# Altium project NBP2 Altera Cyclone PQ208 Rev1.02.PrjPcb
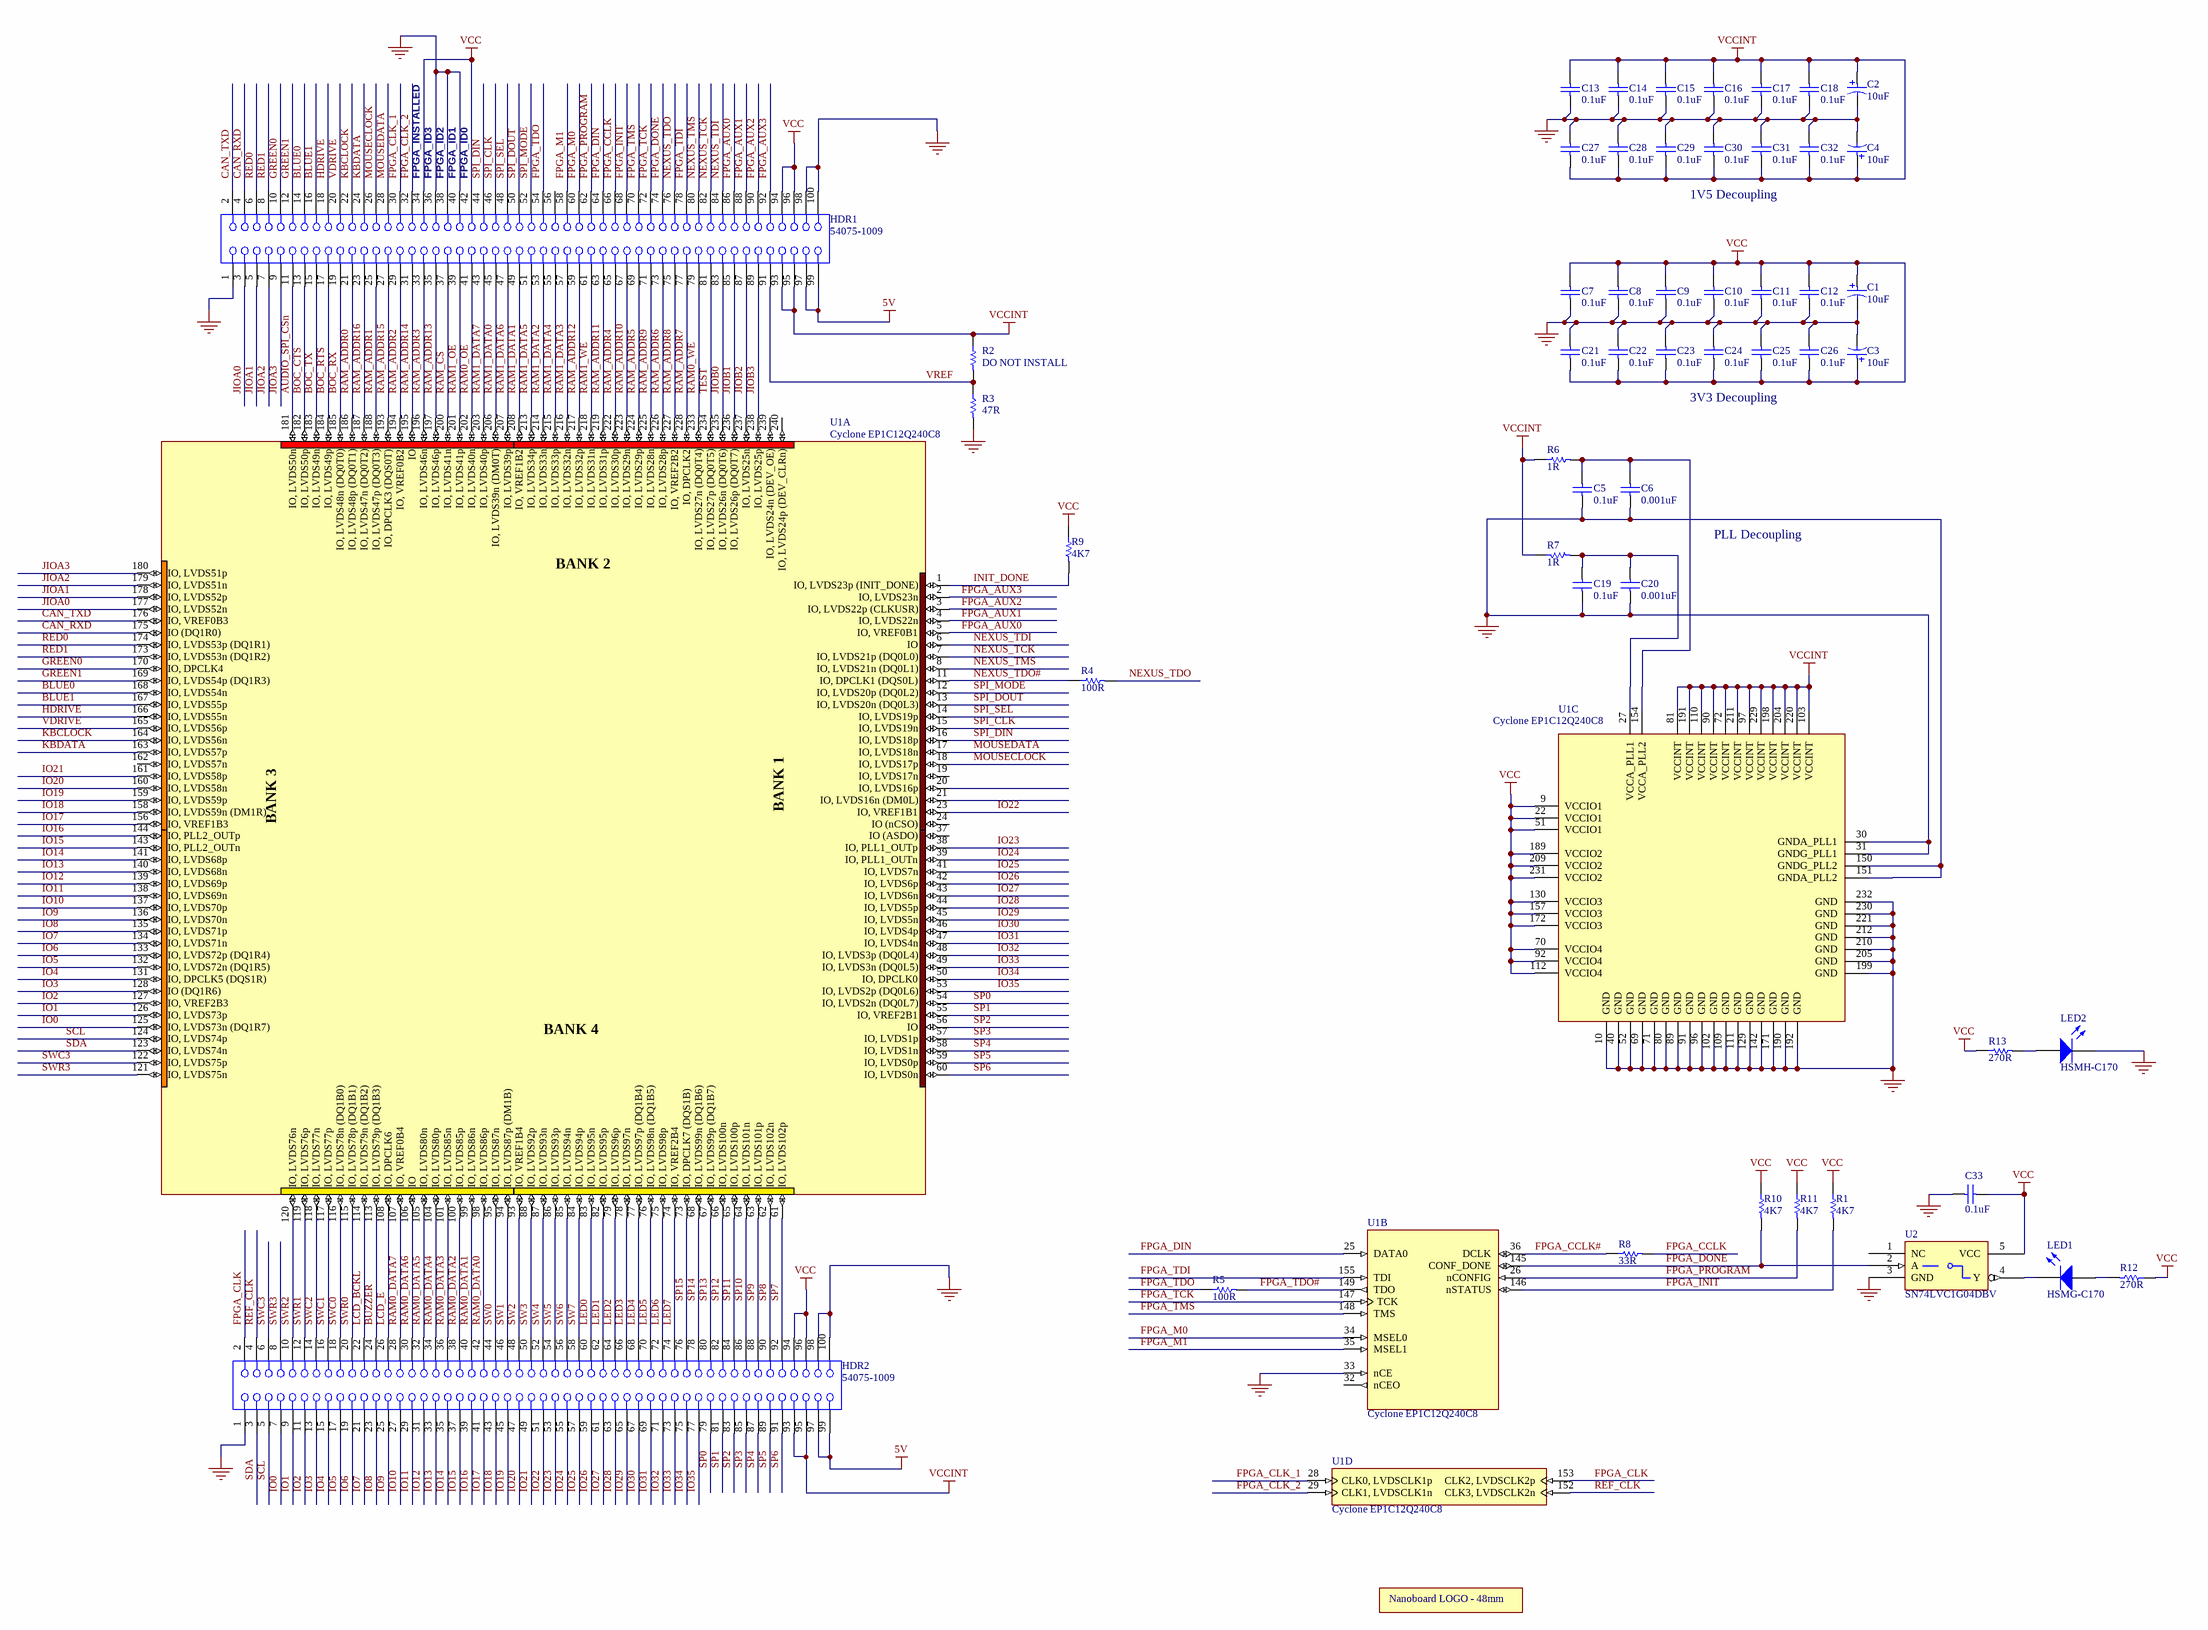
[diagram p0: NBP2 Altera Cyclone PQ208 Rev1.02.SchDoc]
1 sheet, 53 parts. Net scope: global (net labels, ports and power ports of the same name join across sheets).
Board file: NBP2 Altera Cyclone PQ208 Rev1.02.PcbDoc

## Sheet NBP2 Altera Cyclone PQ208 Rev1.02.SchDoc: Cyclone EP1C12 Daughterboard
size C; Organization: Altium Limited; Address1: L3, 12a Rodborough Rd; Address2: Frenchs Forest; Address3: NSW; Address4: Australia 2086; DocumentNumber: 1; Revision: 1.02; SheetNumber: 1; SheetTotal: 1

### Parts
?  NanoboardLogo48mm  [NanoBoard1_LOGO]  (value not drawn)  (graphical)
C1  10uF  [MCCT-B]
C2  10uF  [MCCT-B]
C3  10uF  [MCCT-B]
C4  10uF  [MCCT-B]
C5  0.1uF  [CC2012-0805]
C6  0.001uF  [CC2012-0805]
C7  0.1uF  [CC2012-0805]
C8  0.1uF  [CC2012-0805]
C9  0.1uF  [CC2012-0805]
C10  0.1uF  [CC2012-0805]
C11  0.1uF  [CC2012-0805]
C12  0.1uF  [CC2012-0805]
C13  0.1uF  [CC2012-0805]
C14  0.1uF  [CC2012-0805]
C15  0.1uF  [CC2012-0805]
C16  0.1uF  [CC2012-0805]
C17  0.1uF  [CC2012-0805]
C18  0.1uF  [CC2012-0805]
C19  0.1uF  [CC2012-0805]
C20  0.001uF  [CC2012-0805]
C21  0.1uF  [CC2012-0805]
C22  0.1uF  [CC2012-0805]
C23  0.1uF  [CC2012-0805]
C24  0.1uF  [CC2012-0805]
C25  0.1uF  [CC2012-0805]
C26  0.1uF  [CC2012-0805]
C27  0.1uF  [CC2012-0805]
C28  0.1uF  [CC2012-0805]
C29  0.1uF  [CC2012-0805]
C30  0.1uF  [CC2012-0805]
C31  0.1uF  [CC2012-0805]
C32  0.1uF  [CC2012-0805]
C33  0.1uF  [CC2012-0805]
HDR1  54075-1009  [54075]
HDR2  54075-1009  [54075]
LED1  HSMG-C170  [SMD _LED]
LED2  HSMH-C170  [SMD _LED]
R1  4K7  [CC2012-0805]
R2  DO NOT INSTALL  [CC2012-0805]
R3  47R  [CC2012-0805]
R4  100R  [CC2012-0805]
R5  100R  [CC2012-0805]
R6  1R  [CC2012-0805]
R7  1R  [CC2012-0805]
R8  33R  [CC2012-0805]
R9  4K7  [CC2012-0805]
R10  4K7  [CC2012-0805]
R11  4K7  [CC2012-0805]
R12  270R  [CC2012-0805]
R13  270R  [CC2012-0805]
U1  Cyclone EP1C12Q240C8  [F-QFP32X32-G240/P.5N(RS)]  (parts A,B,C,D of 4)
U2  SN74LVC1G04DBV  [SO-G5/P.95]

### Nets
5V: HDR1.97 HDR1.99 HDR2.97 HDR2.99
GND: C1.2 C2.2 C3.2 C4.2 C5.2 C6.2 C7.2 C8.2 C9.2 C10.2 C11.2 C12.2 C13.2 C14.2 C15.2 C16.2 C17.2 C18.2 C19.1 C20.1 C21.1 C22.1 C23.1 C24.1 C25.1 C26.1 C27.1 C28.1 C29.1 C30.1 C31.1 C32.1 C33.2 HDR1.1 HDR1.36 HDR1.38 HDR1.40 HDR1.98 HDR1.100 HDR2.1 HDR2.98 HDR2.100 LED2.2(K) R3.2 U1.10(GND) U1.30(GNDA_PLL1) U1.31(GNDG_PLL1) U1.33(nCE) U1.40(GND) U1.52(GND) U1.69(GND) U1.71(GND) U1.80(GND) U1.89(GND) U1.91(GND) U1.96(GND) U1.102(GND) U1.109(GND) U1.111(GND) U1.129(GND) U1.142(GND) U1.150(GNDG_PLL2) U1.151(GNDA_PLL2) U1.171(GND) U1.190(GND) U1.192(GND) U1.199(GND) U1.205(GND) U1.210(GND) U1.212(GND) U1.221(GND) U1.230(GND) U1.232(GND) U2.3(GND)
VCC: C1.1 C3.1 C7.1 C8.1 C9.1 C10.1 C11.1 C12.1 C21.2 C22.2 C23.2 C24.2 C25.2 C26.2 C33.1 HDR1.34 HDR1.42 HDR1.94 HDR1.96 HDR2.94 HDR2.96 R1.1 R9.1 R10.1 R11.1 R12.1 R13.1 U1.9(VCCIO1) U1.22(VCCIO1) U1.51(VCCIO1) U1.70(VCCIO4) U1.92(VCCIO4) U1.112(VCCIO4) U1.130(VCCIO3) U1.157(VCCIO3) U1.172(VCCIO3) U1.189(VCCIO2) U1.209(VCCIO2) U1.231(VCCIO2) U2.5(VCC)
VCCINT: C2.1 C4.1 C13.1 C14.1 C15.1 C16.1 C17.1 C18.1 C27.2 C28.2 C29.2 C30.2 C31.2 C32.2 HDR1.93 HDR1.95 HDR2.93 HDR2.95 R2.1 R6.1 R7.1 U1.72(VCCINT) U1.81(VCCINT) U1.90(VCCINT) U1.97(VCCINT) U1.103(VCCINT) U1.110(VCCINT) U1.191(VCCINT) U1.198(VCCINT) U1.204(VCCINT) U1.211(VCCINT) U1.220(VCCINT) U1.229(VCCINT)
AUDIO_SPI_CSn: HDR1.11 U1.181(IO,_LVDS50n)
BLUE0: HDR1.14 U1.168(IO,_LVDS54n)
BLUE1: HDR1.16 U1.167(IO,_LVDS55p)
BOC_CTS: HDR1.13 U1.182(IO,_LVDS50p)
BOC_RTS: HDR1.17 U1.184(IO,_LVDS49p)
BOC_RX: HDR1.19 U1.185(IO,_LVDS48n_(DQ0T0))
BOC_TX: HDR1.15 U1.183(IO,_LVDS49n)
BUZZER: HDR2.24 U1.113(IO,_LVDS79p_(DQ1B3))
CAN_RXD: HDR1.4 U1.175(IO_(DQ1R0))
CAN_TXD: HDR1.2 U1.176(IO,_VREF0B3)
FPGA_AUX0: HDR1.86 U1.5(IO,_VREF0B1)
FPGA_AUX1: HDR1.88 U1.4(IO,_LVDS22n)
FPGA_AUX2: HDR1.90 U1.3(IO,_LVDS22p_(CLKUSR))
FPGA_AUX3: HDR1.92 U1.2(IO,_LVDS23n)
FPGA_CCLK: HDR1.66 R8.2
FPGA_CCLK#: R8.1 U1.36(DCLK)
FPGA_CLK: HDR2.2 U1.153(CLK2,_LVDSCLK2p)
FPGA_CLK_1: HDR1.30 U1.28(CLK0,_LVDSCLK1p)
FPGA_CLK_2: HDR1.32 U1.29(CLK1,_LVDSCLK1n)
FPGA_DIN: HDR1.64 U1.25(DATA0)
FPGA_DONE: HDR1.74 R10.2 U1.145(CONF_DONE) U2.2(A)
FPGA_INIT: HDR1.68 R1.2 U1.146(nSTATUS)
FPGA_M0: HDR1.60 U1.34(MSEL0)
FPGA_M1: HDR1.58 U1.35(MSEL1)
FPGA_PROGRAM: HDR1.62 R11.2 U1.26(nCONFIG)
FPGA_TCK: HDR1.72 U1.147(TCK)
FPGA_TDI: HDR1.78 U1.155(TDI)
FPGA_TDO: HDR1.54 R5.1
FPGA_TDO#: R5.2 U1.149(TDO)
FPGA_TMS: HDR1.70 U1.148(TMS)
GREEN0: HDR1.10 U1.170(IO,_DPCLK4)
GREEN1: HDR1.12 U1.169(IO,_LVDS54p_(DQ1R3))
HDRIVE: HDR1.18 U1.166(IO,_LVDS55n)
INIT_DONE: R9.2 U1.1(IO,_LVDS23p_(INIT_DONE))
IO0: HDR2.7 U1.125(IO,_LVDS73n_(DQ1R7))
IO1: HDR2.9 U1.126(IO,_LVDS73p)
IO2: HDR2.11 U1.127(IO,_VREF2B3)
IO3: HDR2.13 U1.128(IO_(DQ1R6))
IO4: HDR2.15 U1.131(IO,_DPCLK5_(DQS1R))
IO5: HDR2.17 U1.132(IO,_LVDS72n_(DQ1R5))
IO6: HDR2.19 U1.133(IO,_LVDS72p_(DQ1R4))
IO7: HDR2.21 U1.134(IO,_LVDS71n)
IO8: HDR2.23 U1.135(IO,_LVDS71p)
IO9: HDR2.25 U1.136(IO,_LVDS70n)
IO10: HDR2.27 U1.137(IO,_LVDS70p)
IO11: HDR2.29 U1.138(IO,_LVDS69n)
IO12: HDR2.31 U1.139(IO,_LVDS69p)
IO13: HDR2.33 U1.140(IO,_LVDS68n)
IO14: HDR2.35 U1.141(IO,_LVDS68p)
IO15: HDR2.37 U1.143(IO,_PLL2_OUTn)
IO16: HDR2.39 U1.144(IO,_PLL2_OUTp)
IO17: HDR2.41 U1.156(IO,_VREF1B3)
IO18: HDR2.43 U1.158(IO,_LVDS59n_(DM1R))
IO19: HDR2.45 U1.159(IO,_LVDS59p)
IO20: HDR2.47 U1.160(IO,_LVDS58n)
IO21: HDR2.49 U1.161(IO,_LVDS58p)
IO22: HDR2.51 U1.23(IO,_VREF1B1)
IO23: HDR2.53 U1.38(IO,_PLL1_OUTp)
IO24: HDR2.55 U1.39(IO,_PLL1_OUTn)
IO25: HDR2.57 U1.41(IO,_LVDS7n)
IO26: HDR2.59 U1.42(IO,_LVDS6p)
IO27: HDR2.61 U1.43(IO,_LVDS6n)
IO28: HDR2.63 U1.44(IO,_LVDS5p)
IO29: HDR2.65 U1.45(IO,_LVDS5n)
IO30: HDR2.67 U1.46(IO,_LVDS4p)
IO31: HDR2.69 U1.47(IO,_LVDS4n)
IO32: HDR2.71 U1.48(IO,_LVDS3p_(DQ0L4))
IO33: HDR2.73 U1.49(IO,_LVDS3n_(DQ0L5))
IO34: HDR2.75 U1.50(IO,_DPCLK0)
IO35: HDR2.77 U1.53(IO,_LVDS2p_(DQ0L6))
JIOA0: HDR1.3 U1.177(IO,_LVDS52n)
JIOA1: HDR1.5 U1.178(IO,_LVDS52p)
JIOA2: HDR1.7 U1.179(IO,_LVDS51n)
JIOA3: HDR1.9 U1.180(IO,_LVDS51p)
JIOB0: HDR1.83 U1.235(IO,_LVDS26n_(DQ0T6))
JIOB1: HDR1.85 U1.236(IO,_LVDS26p_(DQ0T7))
JIOB2: HDR1.87 U1.237(IO,_LVDS25n)
JIOB3: HDR1.89 U1.238(IO,_LVDS25p)
KBCLOCK: HDR1.22 U1.164(IO,_LVDS56n)
KBDATA: HDR1.24 U1.163(IO,_LVDS57p)
LCD_BCKL: HDR2.22 U1.114(IO,_LVDS79n_(DQ1B2))
LCD_E: HDR2.26 U1.108(IO,_DPCLK6)
LED0: HDR2.60 U1.83(IO,_LVDS95n)
LED1: HDR2.62 U1.82(IO,_LVDS95p)
LED2: HDR2.64 U1.79(IO,_LVDS96p)
LED3: HDR2.66 U1.78(IO,_LVDS97n)
LED4: HDR2.68 U1.77(IO,_LVDS97p_(DQ1B4))
LED5: HDR2.70 U1.76(IO,_LVDS98n_(DQ1B5))
LED6: HDR2.72 U1.75(IO,_LVDS98p)
LED7: HDR2.74 U1.74(IO,_VREF2B4)
MOUSECLOCK: HDR1.26 U1.18(IO,_LVDS17p)
MOUSEDATA: HDR1.28 U1.17(IO,_LVDS18n)
NEXUS_TCK: HDR1.82 U1.7(IO,_LVDS21p_(DQ0L0))
NEXUS_TDI: HDR1.84 U1.6(IO)
NEXUS_TDO: HDR1.76 R4.2
NEXUS_TDO#: R4.1 U1.11(IO,_DPCLK1_(DQS0L))
NEXUS_TMS: HDR1.80 U1.8(IO,_LVDS21n_(DQ0L1))
RAM0_DATA0: HDR2.42 U1.98(IO,_LVDS86p)
RAM0_DATA1: HDR2.40 U1.99(IO,_LVDS86n)
RAM0_DATA2: HDR2.38 U1.100(IO,_LVDS85p)
RAM0_DATA3: HDR2.36 U1.101(IO,_LVDS85n)
RAM0_DATA4: HDR2.34 U1.104(IO,_LVDS80p)
RAM0_DATA5: HDR2.32 U1.105(IO,_LVDS80n)
RAM0_DATA6: HDR2.30 U1.106(IO)
RAM0_DATA7: HDR2.28 U1.107(IO,_VREF0B4)
RAM0_OE: HDR1.41 U1.202(IO,_LVDS40n)
RAM0_WE: HDR1.79 U1.233(IO,_LVDS27n_(DQ0T4))
RAM1_DATA0: HDR1.45 U1.206(IO,_LVDS39n_(DM0T))
RAM1_DATA1: HDR1.49 U1.208(IO,_VREF1B2)
RAM1_DATA2: HDR1.53 U1.214(IO,_LVDS33n)
RAM1_DATA3: HDR1.57 U1.216(IO,_LVDS32n)
RAM1_DATA4: HDR1.55 U1.215(IO,_LVDS33p)
RAM1_DATA5: HDR1.51 U1.213(IO,_LVDS34p)
RAM1_DATA6: HDR1.47 U1.207(IO,_LVDS39p)
RAM1_DATA7: HDR1.43 U1.203(IO,_LVDS40p)
RAM1_OE: HDR1.39 U1.201(IO,_LVDS41p)
RAM1_WE: HDR1.61 U1.218(IO,_LVDS31n)
RAM_ADDR0: HDR1.21 U1.186(IO,_LVDS48p_(DQ0T1))
RAM_ADDR1: HDR1.25 U1.188(IO,_LVDS47p_(DQ0T3))
RAM_ADDR2: HDR1.29 U1.194(IO,_VREF0B2)
RAM_ADDR3: HDR1.33 U1.196(IO,_LVDS46n)
RAM_ADDR4: HDR1.65 U1.222(IO,_LVDS30p)
RAM_ADDR5: HDR1.69 U1.224(IO,_LVDS29p)
RAM_ADDR6: HDR1.73 U1.226(IO,_LVDS28p)
RAM_ADDR7: HDR1.77 U1.228(IO,_DPCLK2)
RAM_ADDR8: HDR1.75 U1.227(IO,_VREF2B2)
RAM_ADDR9: HDR1.71 U1.225(IO,_LVDS28n)
RAM_ADDR10: HDR1.67 U1.223(IO,_LVDS29n)
RAM_ADDR11: HDR1.63 U1.219(IO,_LVDS31p)
RAM_ADDR12: HDR1.59 U1.217(IO,_LVDS32p)
RAM_ADDR13: HDR1.35 U1.197(IO,_LVDS46p)
RAM_ADDR14: HDR1.31 U1.195(IO)
RAM_ADDR15: HDR1.27 U1.193(IO,_DPCLK3_(DQS0T))
RAM_ADDR16: HDR1.23 U1.187(IO,_LVDS47n_(DQ0T2))
RAM_CS: HDR1.37 U1.200(IO,_LVDS41n)
RED0: HDR1.6 U1.174(IO,_LVDS53p_(DQ1R1))
RED1: HDR1.8 U1.173(IO,_LVDS53n_(DQ1R2))
REF_CLK: HDR2.4 U1.152(CLK3,_LVDSCLK2n)
SCL: HDR2.5 U1.124(IO,_LVDS74p)
SDA: HDR2.3 U1.123(IO,_LVDS74n)
SP0: HDR2.79 U1.54(IO,_LVDS2n_(DQ0L7))
SP1: HDR2.81 U1.55(IO,_VREF2B1)
SP2: HDR2.83 U1.56(IO)
SP3: HDR2.85 U1.57(IO,_LVDS1p)
SP4: HDR2.87 U1.58(IO,_LVDS1n)
SP5: HDR2.89 U1.59(IO,_LVDS0p)
SP6: HDR2.91 U1.60(IO,_LVDS0n)
SP7: HDR2.92 U1.61(IO,_LVDS102p)
SP8: HDR2.90 U1.62(IO,_LVDS102n)
SP9: HDR2.88 U1.63(IO,_LVDS101p)
SP10: HDR2.86 U1.64(IO,_LVDS101n)
SP11: HDR2.84 U1.65(IO,_LVDS100p)
SP12: HDR2.82 U1.66(IO,_LVDS100n)
SP13: HDR2.80 U1.67(IO,_LVDS99p_(DQ1B7))
SP14: HDR2.78 U1.68(IO,_LVDS99n_(DQ1B6))
SP15: HDR2.76 U1.73(IO,_DPCLK7_(DQS1B))
SPI_CLK: HDR1.46 U1.15(IO,_LVDS19n)
SPI_DIN: HDR1.44 U1.16(IO,_LVDS18p)
SPI_DOUT: HDR1.50 U1.13(IO,_LVDS20n_(DQ0L3))
SPI_MODE: HDR1.52 U1.12(IO,_LVDS20p_(DQ0L2))
SPI_SEL: HDR1.48 U1.14(IO,_LVDS19p)
SW0: HDR2.44 U1.95(IO,_LVDS87n)
SW1: HDR2.46 U1.94(IO,_LVDS87p_(DM1B))
SW2: HDR2.48 U1.93(IO,_VREF1B4)
SW3: HDR2.50 U1.88(IO,_LVDS92p)
SW4: HDR2.52 U1.87(IO,_LVDS93n)
SW5: HDR2.54 U1.86(IO,_LVDS93p)
SW6: HDR2.56 U1.85(IO,_LVDS94n)
SW7: HDR2.58 U1.84(IO,_LVDS94p)
SWC0: HDR2.18 U1.116(IO,_LVDS78n_(DQ1B0))
SWC1: HDR2.16 U1.117(IO,_LVDS77p)
SWC2: HDR2.14 U1.118(IO,_LVDS77n)
SWC3: HDR2.6 U1.122(IO,_LVDS75p)
SWR0: HDR2.20 U1.115(IO,_LVDS78p_(DQ1B1))
SWR1: HDR2.12 U1.119(IO,_LVDS76p)
SWR2: HDR2.10 U1.120(IO,_LVDS76n)
SWR3: HDR2.8 U1.121(IO,_LVDS75n)
TEST: HDR1.81 U1.234(IO,_LVDS27p_(DQ0T5))
VDRIVE: HDR1.20 U1.165(IO,_LVDS56p)
VREF: HDR1.91 R2.2 R3.1
NetC5_1: C5.1 C6.1 R6.2 U1.154(VCCA_PLL2)
NetC19_2: C19.2 C20.2 R7.2 U1.27(VCCA_PLL1)
NetLED1_1: LED1.1(A) R12.2
NetLED1_2: LED1.2(K) U2.4(Y)
NetLED2_1: LED2.1(A) R13.2

Not connected (* = marked no-connect by the designer): HDR1 56; U1 19(IO,_LVDS17n) 20(IO,_LVDS16p) 21(IO,_LVDS16n_(DM0L)) 24(IO_(nCSO)) 32(nCEO) 37(IO_(ASDO)) 162(IO,_LVDS57n) 239(IO,_LVDS24n_(DEV_OE)) 240(IO,_LVDS24p_(DEV_CLRn)); U2 1(NC)

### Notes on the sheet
- (near HDR1) FPGA_INSTALLED
- (near HDR1) FPGA_ID3
- (near HDR1) FPGA_ID2
- (near HDR1) FPGA_ID1
- (near HDR1) FPGA_ID0
- 1V5 Decoupling
- 3V3 Decoupling
- PLL Decoupling

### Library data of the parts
C1-C4 = CAP_POLAR: Polar Capacitor
C5-C33 = CAP: Capacitor
HDR1 HDR2 = 54075-1009: Board-to-Board, Docking Station, 0.80mm (.031") Pitch, Shielded Receptacle, Vertical, Ultra Low Profile, SMT; Manufacturer: Molex; Package Information: Latest Revision: Jun-2001; Mating Height: 8.5mm; Voltage: 100V; Current: 0.5A; Contact Resistance: 40mOhm max; PCB Layout: Complies with Manufacturer's Recommendation.
LED1 LED2 = HSMX-C670: Typical RED GaAs SMD LED Agilent make; Manufacturer: Generic Components; Class I: Optoelectronic; Fitted: True
R1-R13 = RES: Resistor
U1 = EP1C12Q240C6_ALT: Cyclone Family, 1.5V FPGA, 173 I/O Pins, 2 x PLLs, Commercial Grade, Speed Grade 6; Manufacturer: Altera; Package Information: Latest Revision: ver11.0, Feb-2003; Class I: Field Programmable Gate Array
U2 = SN74AHC1G04DBVR: Manufacturer: TI; Fitted: True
